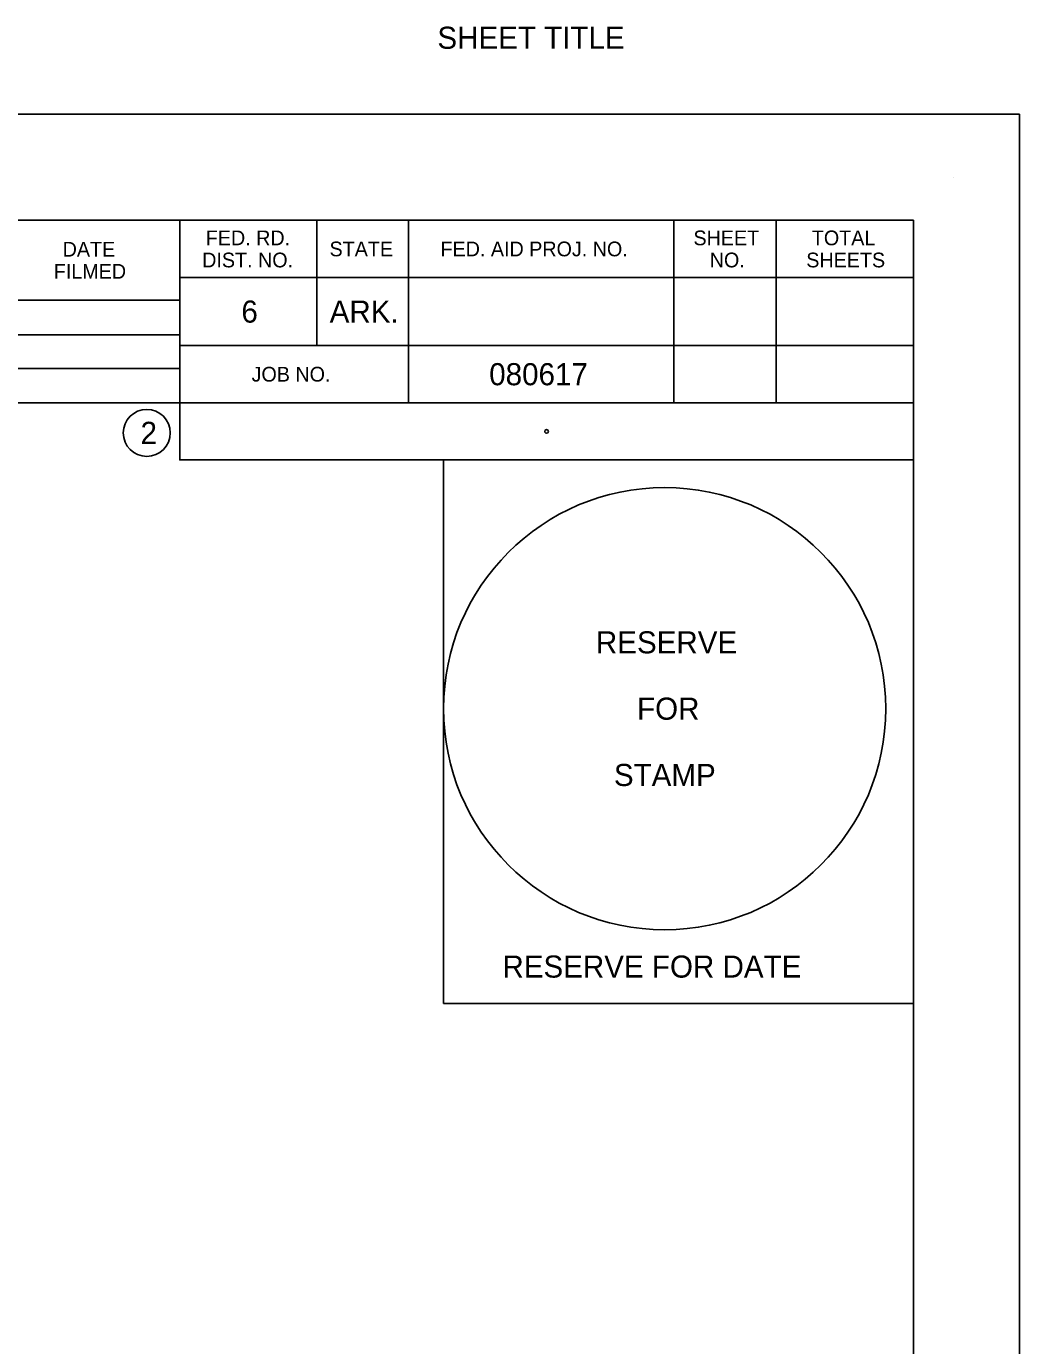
# Model space of a CAD drawing. Extents: x 0 to 762217, y -63 to 1662473.
# Drawn here: x 1430.5 to 1700, y 765.7 to 1123.8 of the extents above; entities that cross this region are included whole.
import ezdxf

# ---------------------------------------------------------------- set-up
doc = ezdxf.new("R2010")
doc.units = 0
for name, color, linetype in [('G-ANNO-TEXT', 7, 'Continuous'), ('G-Border-Paper', 7, 'Continuous'), ('G-Border-Sheet', 7, 'Continuous'), ('G-No Plot-Anchor', 7, 'Continuous'), ('G-No Plot-Border', 7, 'Continuous'), ('G-No Plot-Border-2', 7, 'Continuous'), ('G-No Plot-Stamp', 7, 'Continuous'), ('G-Table-Major', 7, 'Continuous'), ('G-Table-Minor', 7, 'Continuous')]:
    doc.layers.add(name, color=color, linetype=linetype)

msp = doc.modelspace()

# ---------------------------------------------------------------- linework, layer by layer
at = {"layer": 'G-ANNO-TEXT'}
msp.add_line((1682.15, 1082.69), (1682.15, 1082.69), dxfattribs=at)
at = {"layer": 'G-Border-Paper'}
msp.add_lwpolyline([(1700.05, 1100), (0.05, 1100), (0.05, 0), (1700.05, 0)], close=True, dxfattribs=at)
at = {"layer": 'G-Border-Sheet'}
for p in [(75.85, 1071.16), (1671.21, 28.84)]:
    msp.add_line(p, (1671.21, 1071.16), dxfattribs=at)
at = {"layer": 'G-No Plot-Anchor'}
msp.add_circle((1571.66, 1013.86), 0.5, dxfattribs=at)
at = {"layer": 'G-No Plot-Border'}
msp.add_lwpolyline([(75.85, 543.54), (75.85, 1071.16), (1273.86, 1071.16), (1273.86, 1021.61), (1472.11, 1021.61), (1472.11, 1006.11), (1543.71, 1006.11), (1543.71, 858.61), (1671.21, 858.61), (1671.21, 543.54)], close=True, dxfattribs=at)
at = {"layer": 'G-No Plot-Border-2'}
msp.add_lwpolyline([(75.85, 1071.16), (1147.43, 1071.16), (1147.43, 923.66), (1273.86, 923.66), (1273.86, 1021.61), (1472.11, 1021.61), (1472.11, 1006.11), (1671.21, 1006.11), (1671.21, 543.54), (75.85, 543.54)], close=True, dxfattribs=at)
at = {"layer": 'G-No Plot-Stamp'}
msp.add_circle((1603.71, 938.61), 60, dxfattribs=at)
at = {"layer": 'G-Table-Major'}
for p, q in [((1472.11, 1071.16), (1472.11, 1006.11)), ((1273.86, 1049.46), (1472.11, 1049.46)), ((1671.21, 1021.61), (1273.86, 1021.61)), ((1472.11, 1006.11), (1671.21, 1006.11))]:
    msp.add_line(p, q, dxfattribs=at)
msp.add_lwpolyline([(1520.43, 1006.11), (1671.21, 1006.11), (1671.21, 831.94)], dxfattribs=at)
msp.add_circle((1463.17, 1013.47), 6.38, dxfattribs=at)
at = {"layer": 'G-Table-Minor'}
for p, q in [((1509.31, 1071.16), (1509.31, 1037.16)), ((1534.16, 1071.16), (1534.16, 1021.76)), ((1606.21, 1071.16), (1606.21, 1021.76)), ((1634.01, 1071.16), (1634.01, 1021.76)), ((1671.21, 1056.56), (1671.21, 1056.56)), ((1671.21, 1055.61), (1472.11, 1055.61)), ((1273.86, 1040.11), (1472.11, 1040.11)), ((1671.21, 1037.16), (1472.11, 1037.16)), ((1273.86, 1030.96), (1472.11, 1030.96))]:
    msp.add_line(p, q, dxfattribs=at)

# ---------------------------------------------------------------- texts
at = {"layer": 'G-ANNO-TEXT'}
for s, height, p in [('SHEET TITLE', 6, (1542.03, 1117.71)), ('FED. RD.', 4, (1479.18, 1064.39)), ('SHEET', 4, (1611.53, 1064.39)), ('TOTAL', 4, (1643.66, 1064.39)), ('DATE', 4, (1440.33, 1061.31)), ('STATE', 4, (1512.76, 1061.39)), ('FED. AID PROJ. NO.', 4, (1542.88, 1061.39)), ('DIST. NO.', 4, (1478.2, 1058.39)), ('NO.', 4, (1615.95, 1058.39)), ('SHEETS', 4, (1642.15, 1058.39)), ('FILMED', 4, (1437.93, 1055.31)), ('6', 6, (1488.84, 1043.39)), ('ARK.', 6, (1512.8, 1043.39)), ('JOB NO.', 4, (1491.61, 1027.39)), ('080617', 6, (1556.1, 1026.39)), ('2', 6, (1461.47, 1010.47))]:
    msp.add_text(s, height=height, dxfattribs=at).set_placement(p)
at = {"layer": 'G-No Plot-Stamp'}
for s, p in [('RESERVE', (1585.05, 953.61)), ('FOR ', (1596.22, 935.61)), ('STAMP', (1589.94, 917.61)), ('RESERVE FOR DATE', (1559.68, 865.61))]:
    msp.add_text(s, height=6, dxfattribs=at).set_placement(p)

doc.saveas('drawing.dxf')
